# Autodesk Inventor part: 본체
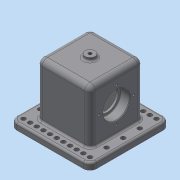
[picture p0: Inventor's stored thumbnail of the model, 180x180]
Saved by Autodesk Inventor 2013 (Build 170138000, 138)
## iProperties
Created: 2018-11
Part Number: 본체
Material: 일반
Document SubType Name: Modeling
Designer: dgall
Density: 1 g/cm^3
Author: dgall
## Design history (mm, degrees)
sketch "스케치1"
  geometry: L1 (0.533, -0.244)-(80.533, -0.244); L2 (80.533, -0.244)-(80.533, 79.756); L3 (80.533, 79.756)-(0.533, 79.756); L4 (0.533, 79.756)-(0.533, -0.244); 1 further point
  constraints: 8 end point, 2 parallel, 2 perpendicular, 1 horizontal
  dimensions: "d0" = 80 distance of L2.end L3.end
extrude "돌출1" new body sketch "스케치1" distance "d2" = 90; taper "d3" = 0 deg
sketch "스케치2"
  geometry: L1 (-0.533, -0.244)-(-0.533, 79.756) reference; L2 (-0.533, 79.756)-(-80.533, 79.756) reference; L3 (-100.533, -20.244)-(19.467, -20.244); L4 (19.467, -20.244)-(19.467, 99.756); L5 (19.467, 99.756)-(-100.533, 99.756); L6 (-100.533, 99.756)-(-100.533, -20.244); 5 further points
  constraints: 8 end point, 4 midpoint, 2 parallel, 2 perpendicular, 1 horizontal, 1 horizontal alignment, 1 vertical alignment
  dimensions: "d4" = 120 distance of L4.end L5.end
extrude "돌출2" join sketch "스케치2" distance "d6" = 10; taper "d7" = 0 deg
sketch "스케치3"
  geometry: L1 (19.467, -20.244)-(19.467, 99.756) reference; L2 (19.467, 99.756)-(-100.533, 99.756) reference; L3 (-63.533, 9.756)-(-17.533, 9.756); L4 (-17.533, 9.756)-(-17.533, 69.756); L5 (-17.533, 69.756)-(-63.533, 69.756); L6 (-63.533, 69.756)-(-63.533, 9.756); L7 (-100.533, -20.244)-(19.467, -20.244) reference; L8 (19.467, -20.244)-(19.467, 99.756) reference; L9 (19.467, 99.756)-(-100.533, 99.756) reference; L10 (-100.533, 99.756)-(-100.533, -20.244) reference; 5 further points
  constraints: 8 end point, 4 midpoint, 2 parallel, 1 horizontal, 1 horizontal alignment, 1 perpendicular, 1 vertical alignment
  dimensions: "d8" = 46 distance of L4.end L5.end; "d10" = 60 distance of L3.end L4.end
extrude "돌출3" cut sketch "스케치3" distance "d11" = 80; taper "d12" = 0 deg
sketch "스케치4"
  geometry: L1 (0, 0)-(0, 80) reference; L2 (80, 0)-(80, 80) reference; L3 (0, 80)-(80, 80) reference; L4 (0, 0)-(0, 80) reference; L5 (0, 0)-(80, 0) reference; L6 (90, 100)-(90, -20) reference; C1 r 20 at (42, 40); 2 further points
  constraints: 1 centre point, 1 horizontal alignment, 1 midpoint
  dimensions: "d13" = 48 distance from line of L6 C1.centre; "d14" = 40 diameter of C1
extrude "돌출4" cut sketch "스케치4" distance "d15" = 14; taper "d16" = 0 deg
sketch "스케치5"
  geometry: C1 r 20 at (0, 0) reference; C2 r 16.5 at (0, 0); 1 further point
  constraints: 1 centre point, 1 coincident
  dimensions: "d17" = 33 diameter of C2
extrude "돌출5" cut sketch "스케치5" distance "d19" = 17; taper "d20" = 0 deg
node "작업 평면1"
sketch "스케치6"
  geometry: L1 (0.533, -0.244)-(80.533, -0.244) reference; L2 (80.533, -0.244)-(80.533, 79.756) reference; L3 (80.533, 79.756)-(0.533, 79.756) reference; L4 (0.533, 79.756)-(0.533, -0.244) reference; C1 r 7.5 at (40.533, 39.756); 3 further points
  constraints: 2 midpoint, 1 centre point, 1 horizontal alignment, 1 vertical alignment
  dimensions: "d22" = 15 diameter of C1
extrude "돌출6" join sketch "스케치6" stored distance "d24" = 17; taper "d25" = 0 deg
node "작업 평면2"
fillet "모깎기1" dims "d26" = 10
sketch "스케치7"
  geometry: C1 r 3.3 at (-9.467, 89.756); A1 r 10 centre (-9.467, 89.756) between (-9.467, 99.756) and (-19.467, 89.756) reference; 1 further point
  constraints: 1 centre point, 1 coincident
  dimensions: "d27" = 6.6 diameter of C1
extrude "돌출7" cut sketch "스케치7" distance "d30" = 17; taper "d31" = 0 deg
node "작업 평면3"
fillet "모깎기2" dims "d38" = 8
fillet "모깎기3" dims "d39" = 3
fillet "모깎기4" dims "d40" = 3
hole "구멍1" diameter "d43" = 4.917; stored, may be unused: countersink angle "d47" = 90 deg, drill point angle "d49" = 118 deg; dims "d41" = 10, "d42" = 10, "d44" = 6, "d45" = 4, "d46" = 2, "d48" = 8
sketch "스케치8" dims "d50" = 52
  geometry: C1 r 20 at (-34, 32) reference; 3 further points
  constraints: 2 horizontal alignment, 1 coincident, 2 other
hole "구멍2" sketch "스케치8" at (-8, 32) diameter "d52" = 3.242; stored, may be unused: countersink angle "d56" = 90 deg, drill point angle "d58" = 118 deg; dims "d53" = 8, "d54" = 4, "d55" = 2, "d57" = 10
node "작업 평면4"
sketch "스케치9"
  geometry: L1 (-18, 82)-(82, 82) reference; L2 (0, 69)-(64, 69) reference; L3 (0, 0)-(0, 69) reference; L4 (64, 0)-(0, 0) reference; L5 (64, 69)-(64, 0) reference; 3 further points
  constraints: 1 midpoint, 1 vertical alignment, 1 other
  dimensions: "d63" = 48 distance from line of L1 point (32, 34)
feature "엠보싱1" sketch "스케치9" dims "d0" = 80, "d64" = 0.5, "d65" = 0
fillet "모깎기5" dims "d66" = 3
fillet "모깎기6" dims "d67" = 0.6
chamfer "모따기1" distance "d68" = 1; stored, may be unused: second distance "d69" = 2, angle "d70" = 45 deg
node "솔리드1"
mirror "대칭1"
pattern_linear "직사각형 패턴1" dims "d34" = 10
mirror "대칭2"
pattern_linear "직사각형 패턴2" dims "d37" = 25
mirror "대칭3"
pattern_circular "원형 패턴1" dims angle "d60" = 360 deg
mirror "대칭4"
node "투영된 루프1"
node "투영된 루프2"
node "투영된 루프3"
node "투영된 루프4"
other parameters: "d21" = -95
